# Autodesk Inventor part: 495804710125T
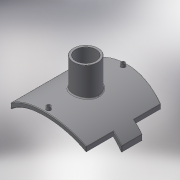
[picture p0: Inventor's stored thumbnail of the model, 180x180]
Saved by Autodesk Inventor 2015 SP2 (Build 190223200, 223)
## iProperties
Created: 2017-10
Part Number: 495804710125T
Material: Generic
Description: PLASSON BRANCH SADDLE 450-800X125
Document SubType Name: Modeling
Designer: KIM
Density: 1 g/cm^3
Appearance: Default
Author: KIM
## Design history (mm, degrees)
derived "495804 (SECOND).ipt"
feature "Solid1::495804 (SECOND).ipt"
tag "TaggingFeature1"
body "Solid1"
other parameters: "d1" = 15, "d2" = 283.5, "d4" = 0, "d5" = 315, "d6" = 75, "d7" = 0, "d8" = 135, "d10" = 0, "d11" = 4, "d12" = 425.6, "d13" = 14, "d14" = 135, "d16" = 5 deg, "d18" = 4, "d19" = 14, "d20" = 0, "d21" = 3, "d22" = 0, "d23" = 524, "d24" = 125, "d25" = 16, "d28" = 0, "d29" = 9.6, "d31" = 0, "d32" = 32.7, "d33" = 0, "d34" = 8, "d35" = 1.6, "d_1" = 125, "B_" = 315, "H_" = 109, "x_" = 15, "D_" = 16
